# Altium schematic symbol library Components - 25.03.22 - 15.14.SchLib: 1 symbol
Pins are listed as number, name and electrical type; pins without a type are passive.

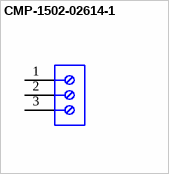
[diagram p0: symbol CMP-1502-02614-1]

## CMP-1502-02614-1
designator J?, comment 691236510003
Serie 2365 - 5.08 mm Horizontal Cable Entry Modular with Rising Cage Clamp WR-TBL, 3 pin; Manufacturer: Wurth Elektronik; Pin Number: 3; Pitch: 5.08mm
footprint 691236510003 (Horizontal Cable Entry with Rising Cage Clamp, pitch 5.08mm, 03p)
pins: 1, 2, 3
